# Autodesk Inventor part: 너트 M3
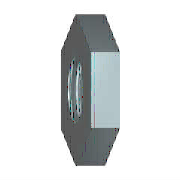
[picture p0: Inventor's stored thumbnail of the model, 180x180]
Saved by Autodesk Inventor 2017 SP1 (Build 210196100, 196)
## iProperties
Created: 2012-02
Part Number: 너트 M3
Material: 강철, 연강
Description: 6각 너트 및 6각 가는 너트 - 모따기 안된
Document SubType Name: Modeling
Standard: KS B 1012
Designer: mduedu
Standards Organization: KS
Language: ko-KR
Size Designation: B  M 3
Categories: <MemberInstance><Categories><Category DisplayName="조임쇠" InternalName="e4da775c-781d-43d5-af7c-5136215cf5a6" Mnemonic="FSTN"><Category DisplayName="너트" InternalN
Density: 7.86 g/cm^3
Mass: 0.300693 g
Surface Area: 0.894003 cm^2
Volume: 0.0382562 cm^3
Appearance: 강철
IsCustomPart: 0
Author: mduedu
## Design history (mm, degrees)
sketch "스케치1"
  geometry: L1 (1.588, -2.75)-(-1.588, -2.75); L2 (-1.588, -2.75)-(-3.175, 0); L3 (-3.175, 0)-(-1.588, 2.75); L4 (-1.588, 2.75)-(1.588, 2.75); L5 (1.588, 2.75)-(3.175, 0); L6 (3.175, 0)-(1.588, -2.75); 2 further points
  constraints: 12 end point, 1 coincident, 1 horizontal, 11 other
  dimensions: "d0" = 6.35085 distance of L5.end L2.end (= 1.1547 x SW)
extrude "본체" new body sketch "스케치1" distance "d1" = 1.8 (= KOH); taper "d2" = 0 deg
sketch "스케치2"
  geometry: 1 further point
hole "스레드" sketch "스케치2" diameter "d3" = 2.459; stored, may be unused: countersink angle "d7" = 82 deg, drill point angle "d9" = 118 deg; dims "d4" = 6, "d5" = 4, "d6" = 2, "d8" = 8
workaxis "Work Axis1"
workplane "Work Plane1"
body "Solid1"
chamfer "모따기2" distance "d12" = 0.27063 (= -0.5 x GD1 + 0.5 x NND); stored, may be unused: angle "d13" = 30 deg, second distance "d19" = 0.27063 (= -0.5 x GD1 + 0.5 x NND)
chamfer "모따기1" distance "d10" = 0.27063 (= -0.5 x GD1 + 0.5 x NND); stored, may be unused: angle "d11" = 30 deg, second distance "d18" = 0.27063 (= -0.5 x GD1 + 0.5 x NND)
other parameters: "NND" = 3 [user parameter; used in 4 equation terms], "KOH" = 1.8 [user parameter; used in 1 equation term], "SW" = 5.5 [user parameter; used in 2 equation terms], "GD1" = 2.45873 (computed from THREADDIA, PTC, TOA) [user parameter; used in 4 equation terms], "d15" = 0, "d17" = 0, "d20" = 0, "d21" = 0, "GUL" = 0.27063 (= 0.541266 x PTC) [user parameter], "THREADDIA" = 3 [user parameter; used in 1 equation term], "TOA" = 30 deg [user parameter; used in 1 equation term], "PTC" = 0.5 [user parameter; used in 4 equation terms], "E0" = 6.3525 (= 1.155 x SW) [user parameter], "GAL" = 0.27063 (= 0.541266 x PTC) [user parameter]
